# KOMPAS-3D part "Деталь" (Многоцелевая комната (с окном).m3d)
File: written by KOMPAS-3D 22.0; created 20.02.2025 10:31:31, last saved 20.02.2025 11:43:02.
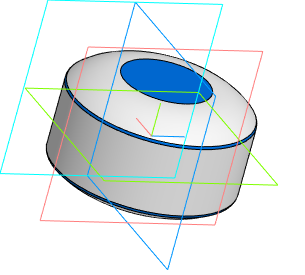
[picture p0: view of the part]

Document properties: Автор: Пользователь Windows; Полное имя файла: C:\Users\Student\Documents\Картошечка\База Сабнатика\Многоцелевая комната\Многоцелевая комната (с окном).m3d

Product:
- Part/product: Деталь
    Масса: 0.417762

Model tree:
1. Эскиз:3
2. Элемент вращения:1
     Угол 1 = 360
3. Скругление:1  (with: Элемент вращения:1)
     Радиус = 1
4. Смещенная плоскость:1
     Расстояние = 25
5. Эскиз:4
6. Элемент выдавливания:1
     Расстояние 2 = 2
